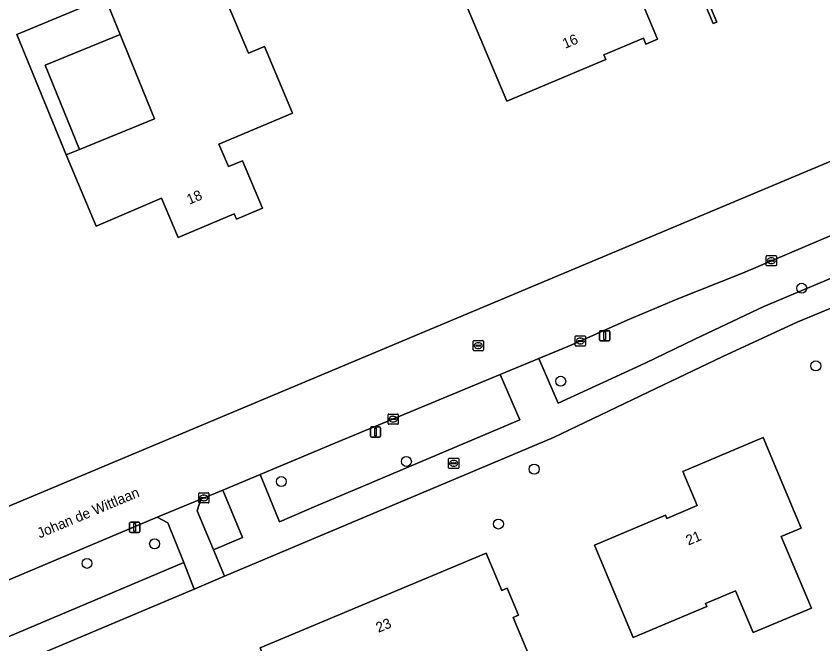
# Model space of a CAD drawing. Extents: x 162417 to 163722, y 384268 to 385417.
# Drawn here: x 163210.5 to 163289.6, y 384911.4 to 384972.9 of the extents above; entities that cross this region are included whole.
import ezdxf

# ---------------------------------------------------------------- set-up
doc = ezdxf.new("R2010")
doc.units = 0
for name, color, linetype in [('IMGEO_Boom', 7, 'Continuous'), ('IMGEO_Brandkraan', 7, 'Continuous'), ('IMGEO_Erf', 7, 'Continuous'), ('IMGEO_Groenvoorziening', 7, 'Continuous'), ('IMGEO_Kolk', 7, 'Continuous'), ('IMGEO_Lichtmast', 7, 'Continuous'), ('IMGEO_Muur', 7, 'Continuous'), ('IMGEO_Openbare_ruimte_label', 7, 'Continuous'), ('IMGEO_Pand', 7, 'Continuous'), ('IMGEO_Pand_nummerreeks', 7, 'Continuous'), ('IMGEO_Rijbaan_lokaal_gesloten', 7, 'Continuous'), ('IMGEO_Rioolput', 7, 'Continuous'), ('IMGEO_Voetpad_open', 7, 'Continuous')]:
    doc.layers.add(name, color=color, linetype=linetype)

msp = doc.modelspace()

# ---------------------------------------------------------------- linework, layer by layer
at = {"layer": 'IMGEO_Boom'}
for centre in [(163287.481, 384946.258), (163288.864, 384938.646), (163263.862, 384937.143), (163248.734, 384929.281), (163261.261, 384928.519), (163236.482, 384927.307), (163257.755, 384923.144), (163224.061, 384921.205), (163217.435, 384919.286)]:
    msp.add_circle(centre, 0.489, dxfattribs=at)
at = {"layer": 'IMGEO_Brandkraan'}
for p, q in [((163252.865, 384928.668), (163252.865, 384929.52)), ((163252.94, 384929.594), (163253.792, 384929.594)), ((163253.124, 384929.088), (163253.124, 384929.1)), ((163253.562, 384929.051), (163253.164, 384929.051)), ((163253.167, 384929.137), (163253.565, 384929.137)), ((163253.353, 384929.374), (163253.378, 384929.374)), ((163253.608, 384929.1), (163253.608, 384929.088)), ((163253.866, 384929.52), (163253.866, 384928.668)), ((163253.792, 384928.594), (163252.94, 384928.594)), ((163253.376, 384928.814), (163253.351, 384928.814))]:
    msp.add_line(p, q, dxfattribs=at)
for points in [[(163252.865, 384928.668), (163252.865, 384929.52)], [(163252.94, 384929.594), (163253.792, 384929.594)], [(163253.866, 384929.52), (163253.866, 384928.668)], [(163253.792, 384928.594), (163252.94, 384928.594)]]:
    msp.add_lwpolyline(points, dxfattribs=at)
for centre, radius, start, end in [((163252.942, 384929.518), 0.0765, 91.55205, 178.44795), ((163252.942, 384929.518), 0.0765, 91.55205, 178.44795), ((163253.164, 384929.097), 0.0403, 85.87752, 175.75265), ((163253.161, 384929.087), 0.0366, 178.93798, 274.71019), ((163253.565, 384929.094), 0.043, 264.86636, 352.45326), ((163253.569, 384929.099), 0.0386, 1.73085, 96.63898), ((163253.79, 384929.518), 0.0765, 1.55205, 88.44795), ((163253.79, 384929.518), 0.0765, 1.55205, 88.44795), ((163252.942, 384928.67), 0.0765, 181.55205, 268.44795), ((163252.942, 384928.67), 0.0765, 181.55205, 268.44795), ((163253.79, 384928.67), 0.0765, 271.55205, 358.44795), ((163253.79, 384928.67), 0.0765, 271.55205, 358.44795)]:
    msp.add_arc(centre, radius, start, end, dxfattribs=at)
for centre, major_axis, ratio, start_param, end_param in [((163253.352, 384929.094), (-0.387, 0.002), 0.722429, 4.712389, 7.853982), ((163253.377, 384929.094), (-0.39, 0.002), 0.717154, 1.570796, 4.712389)]:
    msp.add_ellipse(centre, major_axis=major_axis, ratio=ratio, start_param=start_param, end_param=end_param, dxfattribs=at)
at = {"layer": 'IMGEO_Erf'}
for points in [[(163318.553, 385000), (163308.966, 385023.36), (163277.359, 385010.294), (163269.662, 385007.068), (163253.071, 385000), (163231.527, 384990.762), (163201.717, 384977.798), (163182.103, 384971.2), (163157.341, 384961.784), (163158.508, 384959.069), (163175.467, 384919.624), (163175.758, 384919.851), (163183.667, 384913.961), (163328.962, 384974.963)], [(163248.575, 384988.36), (163256.137, 384991.526), (163267.304, 384996.224), (163272.166, 384984.668), (163273.711, 384985.318), (163275.903, 384980.108), (163279.166, 384972.35), (163278.799, 384972.196), (163275.535, 384979.953), (163270.366, 384977.778), (163273.36, 384970.663), (163272.211, 384970.18), (163271.968, 384970.759), (163268.093, 384969.129), (163268.289, 384968.662), (163258.579, 384964.577), (163254.537, 384974.183), (163262.051, 384977.344), (163258.091, 384986.755), (163250.58, 384983.595)], [(163233.268, 384969.279), (163234.833, 384969.94), (163237.585, 384963.428), (163230.37, 384960.379), (163231.3, 384958.176), (163232.664, 384958.752), (163234.624, 384954.112), (163232.08, 384953.037), (163231.861, 384953.558), (163226.369, 384951.237), (163224.75, 384955.068), (163218.327, 384952.354), (163215.383, 384959.323), (163210.565, 384971.113), (163219.208, 384974.765), (163229.171, 384978.975)], [(163220.693, 384971.128), (163219.208, 384974.765), (163210.565, 384971.113), (163215.383, 384959.323), (163216.704, 384959.862), (163213.332, 384968.124)], [(163224.065, 384962.867), (163220.693, 384971.128), (163213.332, 384968.124), (163216.704, 384959.862)], [(163270.968, 384912.011), (163269.098, 384916.452), (163267.157, 384921.06), (163274.138, 384924), (163274.264, 384923.701), (163277.248, 384924.957), (163275.838, 384928.304), (163283.695, 384931.613), (163285.635, 384927.005), (163287.428, 384922.748), (163285.474, 384921.925), (163288.431, 384914.903), (163282.726, 384912.501), (163281.002, 384916.594), (163278.053, 384915.352), (163278.181, 384915.048)], [(163239.794, 384898.772), (163240.168, 384897.877), (163239.882, 384897.758), (163239.511, 384898.654), (163234.398, 384911.008), (163256.549, 384920.277), (163258.078, 384916.624), (163258.604, 384916.848), (163259.726, 384914.195), (163259.201, 384913.973), (163261.707, 384907.983), (163259.954, 384907.249), (163260.166, 384906.742), (163255.803, 384904.917), (163254.792, 384907.334), (163255.308, 384907.55), (163254.934, 384908.445), (163254.648, 384908.325), (163254.47, 384908.749), (163248.723, 384906.345), (163250.089, 384903.079)]]:
    msp.add_lwpolyline(points, close=True, dxfattribs=at)
msp.add_lwpolyline([(163355.108, 384922.849), (163338.205, 384963.202), (163332.037, 384960.636), (163331.845, 384960.556), (163328.115, 384959.004), (163309.804, 384951.385), (163305.952, 384950.098), (163301.519, 384948.918), (163287.113, 384942.953), (163279.759, 384939.573), (163273.176, 384936.418), (163263.164, 384931.62), (163230.9, 384918.02), (163227.943, 384916.773), (163202.03, 384905.85), (163198.14, 384904.21), (163175.984, 384894.871), (163189.317, 384805.604)], dxfattribs=at)
at = {"layer": 'IMGEO_Groenvoorziening'}
for points in [[(163301.107, 384951.742), (163304.831, 384952.792), (163303.472, 384956.057), (163302.496, 384956.594), (163281.667, 384947.744), (163275.345, 384945.212), (163270.37, 384943.11), (163264.949, 384940.721), (163261.728, 384939.38), (163263.626, 384934.994), (163272.133, 384938.907), (163277.01, 384941.272), (163283.774, 384944.468)], [(163259.852, 384933.342), (163257.919, 384937.794), (163241.735, 384931.056), (163238.069, 384929.529), (163234.402, 384928.003), (163236.298, 384923.37), (163239.927, 384924.92), (163243.638, 384926.483)], [(163232.676, 384921.822), (163230.736, 384926.477), (163228.587, 384925.583), (163228.227, 384924.429), (163229.822, 384920.603)], [(163200.97, 384908.409), (163226.912, 384919.359), (163225.352, 384923.271), (163224.3, 384923.826), (163200.018, 384913.546), (163199.446, 384912.087)]]:
    msp.add_lwpolyline(points, close=True, dxfattribs=at)
at = {"layer": 'IMGEO_Kolk'}
for p, q in [((163284.077, 384949.45), (163284.929, 384949.45)), ((163284.002, 384948.524), (163284.002, 384949.376)), ((163284.261, 384948.944), (163284.261, 384948.956)), ((163284.699, 384948.907), (163284.301, 384948.907)), ((163284.304, 384948.993), (163284.702, 384948.993)), ((163284.513, 384948.67), (163284.488, 384948.67)), ((163284.49, 384949.23), (163284.515, 384949.23)), ((163284.745, 384948.956), (163284.745, 384948.944)), ((163285.003, 384949.376), (163285.003, 384948.524)), ((163284.929, 384948.45), (163284.077, 384948.45)), ((163265.361, 384941.591), (163266.213, 384941.591)), ((163265.286, 384940.665), (163265.286, 384941.517)), ((163265.545, 384941.085), (163265.545, 384941.097)), ((163265.983, 384941.048), (163265.585, 384941.048)), ((163265.588, 384941.134), (163265.986, 384941.134)), ((163265.797, 384940.811), (163265.772, 384940.811)), ((163265.774, 384941.371), (163265.799, 384941.371)), ((163266.029, 384941.097), (163266.029, 384941.085)), ((163266.287, 384941.517), (163266.287, 384940.665)), ((163266.213, 384940.591), (163265.361, 384940.591)), ((163246.936, 384932.998), (163246.936, 384933.85)), ((163247.011, 384933.924), (163247.863, 384933.924)), ((163247.424, 384933.704), (163247.449, 384933.704)), ((163247.937, 384933.85), (163247.937, 384932.998)), ((163247.863, 384932.924), (163247.011, 384932.924)), ((163247.195, 384933.418), (163247.195, 384933.43)), ((163247.633, 384933.381), (163247.235, 384933.381)), ((163247.238, 384933.467), (163247.636, 384933.467)), ((163247.447, 384933.144), (163247.422, 384933.144)), ((163247.679, 384933.43), (163247.679, 384933.418)), ((163228.381, 384925.281), (163228.381, 384926.133)), ((163228.456, 384926.207), (163229.308, 384926.207)), ((163228.683, 384925.75), (163229.081, 384925.75)), ((163228.869, 384925.987), (163228.894, 384925.987)), ((163229.382, 384926.133), (163229.382, 384925.281)), ((163229.308, 384925.207), (163228.456, 384925.207)), ((163228.64, 384925.701), (163228.64, 384925.713)), ((163229.078, 384925.664), (163228.68, 384925.664)), ((163228.892, 384925.427), (163228.867, 384925.427)), ((163229.124, 384925.713), (163229.124, 384925.701))]:
    msp.add_line(p, q, dxfattribs=at)
for points in [[(163284.077, 384949.45), (163284.929, 384949.45)], [(163284.002, 384948.524), (163284.002, 384949.376)], [(163285.003, 384949.376), (163285.003, 384948.524)], [(163284.929, 384948.45), (163284.077, 384948.45)], [(163265.361, 384941.591), (163266.213, 384941.591)], [(163265.286, 384940.665), (163265.286, 384941.517)], [(163266.287, 384941.517), (163266.287, 384940.665)], [(163266.213, 384940.591), (163265.361, 384940.591)], [(163246.936, 384932.998), (163246.936, 384933.85)], [(163247.011, 384933.924), (163247.863, 384933.924)], [(163247.937, 384933.85), (163247.937, 384932.998)], [(163247.863, 384932.924), (163247.011, 384932.924)], [(163228.381, 384925.281), (163228.381, 384926.133)], [(163228.456, 384926.207), (163229.308, 384926.207)], [(163229.382, 384926.133), (163229.382, 384925.281)], [(163229.308, 384925.207), (163228.456, 384925.207)]]:
    msp.add_lwpolyline(points, dxfattribs=at)
for centre, radius, start, end in [((163284.079, 384949.374), 0.0765, 91.55205, 178.44795), ((163284.079, 384949.374), 0.0765, 91.55205, 178.44795), ((163284.927, 384949.374), 0.0765, 1.55205, 88.44795), ((163284.927, 384949.374), 0.0765, 1.55205, 88.44795), ((163284.301, 384948.953), 0.0403, 85.87752, 175.75265), ((163284.298, 384948.943), 0.0366, 178.93798, 274.71019), ((163284.702, 384948.95), 0.043, 264.86636, 352.45326), ((163284.706, 384948.955), 0.0386, 1.73085, 96.63898), ((163284.079, 384948.526), 0.0765, 181.55205, 268.44795), ((163284.079, 384948.526), 0.0765, 181.55205, 268.44795), ((163284.927, 384948.526), 0.0765, 271.55205, 358.44795), ((163284.927, 384948.526), 0.0765, 271.55205, 358.44795), ((163265.363, 384941.515), 0.0765, 91.55205, 178.44795), ((163265.363, 384941.515), 0.0765, 91.55205, 178.44795), ((163266.211, 384941.515), 0.0765, 1.55205, 88.44795), ((163266.211, 384941.515), 0.0765, 1.55205, 88.44795), ((163265.585, 384941.094), 0.0403, 85.87752, 175.75265), ((163265.582, 384941.084), 0.0366, 178.93798, 274.71019), ((163265.986, 384941.091), 0.043, 264.86636, 352.45326), ((163265.99, 384941.096), 0.0386, 1.73085, 96.63898), ((163265.363, 384940.667), 0.0765, 181.55205, 268.44795), ((163265.363, 384940.667), 0.0765, 181.55205, 268.44795), ((163266.211, 384940.667), 0.0765, 271.55205, 358.44795), ((163266.211, 384940.667), 0.0765, 271.55205, 358.44795), ((163247.013, 384933.848), 0.0765, 91.55205, 178.44795), ((163247.013, 384933.848), 0.0765, 91.55205, 178.44795), ((163247.861, 384933.848), 0.0765, 1.55205, 88.44795), ((163247.861, 384933.848), 0.0765, 1.55205, 88.44795), ((163247.013, 384933), 0.0765, 181.55205, 268.44795), ((163247.013, 384933), 0.0765, 181.55205, 268.44795), ((163247.235, 384933.427), 0.0403, 85.87752, 175.75265), ((163247.232, 384933.417), 0.0366, 178.93798, 274.71019), ((163247.636, 384933.424), 0.043, 264.86636, 352.45326), ((163247.64, 384933.429), 0.0386, 1.73085, 96.63898), ((163247.861, 384933), 0.0765, 271.55205, 358.44795), ((163247.861, 384933), 0.0765, 271.55205, 358.44795), ((163228.458, 384926.131), 0.0765, 91.55205, 178.44795), ((163228.458, 384926.131), 0.0765, 91.55205, 178.44795), ((163228.68, 384925.71), 0.0403, 85.87752, 175.75265), ((163229.085, 384925.712), 0.0386, 1.73085, 96.63898), ((163229.306, 384926.131), 0.0765, 1.55205, 88.44795), ((163229.306, 384926.131), 0.0765, 1.55205, 88.44795), ((163228.458, 384925.283), 0.0765, 181.55205, 268.44795), ((163228.458, 384925.283), 0.0765, 181.55205, 268.44795), ((163228.677, 384925.7), 0.0366, 178.93798, 274.71019), ((163229.081, 384925.707), 0.043, 264.86636, 352.45326), ((163229.306, 384925.283), 0.0765, 271.55205, 358.44795), ((163229.306, 384925.283), 0.0765, 271.55205, 358.44795)]:
    msp.add_arc(centre, radius, start, end, dxfattribs=at)
for centre, major_axis, ratio, start_param, end_param in [((163284.489, 384948.95), (-0.387, 0.002), 0.722429, 4.712389, 7.853982), ((163284.514, 384948.95), (-0.39, 0.002), 0.717154, 1.570796, 4.712389), ((163265.773, 384941.091), (-0.387, 0.002), 0.722429, 4.712389, 7.853982), ((163265.798, 384941.091), (-0.39, 0.002), 0.717154, 1.570796, 4.712389), ((163247.423, 384933.424), (-0.387, 0.002), 0.722429, 4.712389, 7.853982), ((163247.448, 384933.424), (-0.39, 0.002), 0.717154, 1.570796, 4.712389), ((163228.868, 384925.707), (-0.387, 0.002), 0.722429, 4.712389, 7.853982), ((163228.893, 384925.707), (-0.39, 0.002), 0.717154, 1.570796, 4.712389)]:
    msp.add_ellipse(centre, major_axis=major_axis, ratio=ratio, start_param=start_param, end_param=end_param, dxfattribs=at)
at = {"layer": 'IMGEO_Lichtmast'}
for p, q in [((163267.672, 384941.193), (163267.672, 384941.993)), ((163267.672, 384941.993), (163267.672, 384941.193)), ((163267.772, 384942.093), (163268.562, 384942.093)), ((163268.562, 384942.093), (163267.772, 384942.093)), ((163268.662, 384941.993), (163268.662, 384941.193)), ((163268.662, 384941.193), (163268.662, 384941.993)), ((163268.562, 384941.093), (163267.772, 384941.093)), ((163267.772, 384941.093), (163268.562, 384941.093)), ((163245.212, 384931.755), (163245.212, 384932.555)), ((163245.212, 384932.555), (163245.212, 384931.755)), ((163245.312, 384932.655), (163246.102, 384932.655)), ((163246.102, 384932.655), (163245.312, 384932.655)), ((163246.202, 384932.555), (163246.202, 384931.755)), ((163246.202, 384931.755), (163246.202, 384932.555)), ((163246.102, 384931.655), (163245.312, 384931.655)), ((163245.312, 384931.655), (163246.102, 384931.655)), ((163221.616, 384922.425), (163221.616, 384923.225)), ((163221.616, 384923.225), (163221.616, 384922.425)), ((163221.716, 384923.325), (163222.506, 384923.325)), ((163222.506, 384923.325), (163221.716, 384923.325)), ((163222.606, 384923.225), (163222.606, 384922.425)), ((163222.606, 384922.425), (163222.606, 384923.225)), ((163222.506, 384922.325), (163221.716, 384922.325)), ((163221.716, 384922.325), (163222.506, 384922.325))]:
    msp.add_line(p, q, dxfattribs=at)
for points in [[(163268.092, 384941.968), (163268.242, 384941.968), (163268.242, 384941.218), (163268.092, 384941.218), (163268.092, 384941.968)], [(163245.632, 384932.53), (163245.782, 384932.53), (163245.782, 384931.78), (163245.632, 384931.78), (163245.632, 384932.53)], [(163222.036, 384923.2), (163222.186, 384923.2), (163222.186, 384922.45), (163222.036, 384922.45), (163222.036, 384923.2)]]:
    msp.add_lwpolyline(points, dxfattribs=at)
for centre, start, end in [((163267.772, 384941.993), 90, 180), ((163267.772, 384941.993), 90, 180), ((163268.562, 384941.993), 0, 90), ((163268.562, 384941.993), 360, 90), ((163267.772, 384941.193), 180, 270), ((163267.772, 384941.193), 180, 270), ((163268.562, 384941.193), 270, 0), ((163268.562, 384941.193), 270, 0), ((163245.312, 384932.555), 90, 180), ((163245.312, 384932.555), 90, 180), ((163246.102, 384932.555), 0, 90), ((163246.102, 384932.555), 360, 90), ((163245.312, 384931.755), 180, 270), ((163245.312, 384931.755), 180, 270), ((163246.102, 384931.755), 270, 0), ((163246.102, 384931.755), 270, 0), ((163221.716, 384923.225), 90, 180), ((163221.716, 384923.225), 90, 180), ((163222.506, 384923.225), 0, 90), ((163222.506, 384923.225), 360, 90), ((163221.716, 384922.425), 180, 270), ((163221.716, 384922.425), 180, 270), ((163222.506, 384922.425), 270, 0), ((163222.506, 384922.425), 270, 0)]:
    msp.add_arc(centre, 0.1, start, end, dxfattribs=at)
at = {"layer": 'IMGEO_Muur'}
msp.add_lwpolyline([(163275.903, 384980.108), (163275.535, 384979.953), (163278.799, 384972.196), (163279.166, 384972.35)], close=True, dxfattribs=at)
at = {"layer": 'IMGEO_Pand'}
for points in [[(163268.289, 384968.662), (163268.093, 384969.129), (163271.968, 384970.759), (163272.211, 384970.18), (163273.36, 384970.663), (163270.366, 384977.778), (163275.535, 384979.953), (163275.903, 384980.108), (163273.711, 384985.318), (163272.166, 384984.668), (163267.304, 384996.224), (163256.137, 384991.526), (163248.575, 384988.36), (163250.58, 384983.595), (163258.091, 384986.755), (163262.051, 384977.344), (163254.537, 384974.183), (163258.579, 384964.577)], [(163237.585, 384963.428), (163234.833, 384969.94), (163233.268, 384969.279), (163229.171, 384978.975), (163219.208, 384974.765), (163220.693, 384971.128), (163224.065, 384962.867), (163216.704, 384959.862), (163215.383, 384959.323), (163218.327, 384952.354), (163224.75, 384955.068), (163226.369, 384951.237), (163231.861, 384953.558), (163232.08, 384953.037), (163234.624, 384954.112), (163232.664, 384958.752), (163231.3, 384958.176), (163230.37, 384960.379)], [(163270.968, 384912.011), (163278.181, 384915.048), (163278.053, 384915.352), (163281.002, 384916.594), (163282.726, 384912.501), (163288.431, 384914.903), (163285.474, 384921.925), (163287.428, 384922.748), (163285.635, 384927.005), (163283.695, 384931.613), (163275.838, 384928.304), (163277.248, 384924.957), (163274.264, 384923.701), (163274.138, 384924), (163267.157, 384921.06), (163269.098, 384916.452)], [(163239.794, 384898.772), (163250.089, 384903.079), (163248.723, 384906.345), (163254.47, 384908.749), (163254.648, 384908.325), (163254.934, 384908.445), (163255.308, 384907.55), (163254.792, 384907.334), (163255.803, 384904.917), (163260.166, 384906.742), (163259.954, 384907.249), (163261.707, 384907.983), (163259.201, 384913.973), (163259.726, 384914.195), (163258.604, 384916.848), (163258.078, 384916.624), (163256.549, 384920.277), (163234.398, 384911.008), (163239.511, 384898.654)]]:
    msp.add_lwpolyline(points, close=True, dxfattribs=at)
at = {"layer": 'IMGEO_Rijbaan_lokaal_gesloten'}
for points in [[(163337.564, 384978.789), (163336.54, 384978.154), (163336.199, 384978.01), (163333.911, 384977.041), (163328.962, 384974.963), (163183.667, 384913.961), (163186.272, 384907.759), (163194.231, 384911.102), (163200.018, 384913.546), (163224.3, 384923.826)], [(163224.3, 384923.826), (163228.587, 384925.583), (163230.736, 384926.477), (163234.402, 384928.003), (163238.069, 384929.529), (163241.735, 384931.056), (163257.919, 384937.794), (163261.728, 384939.38), (163264.949, 384940.721), (163270.37, 384943.11), (163275.345, 384945.212), (163281.667, 384947.744), (163302.496, 384956.594), (163307.598, 384958.773), (163324.469, 384965.836), (163329.492, 384967.896), (163329.596, 384967.938), (163335.648, 384970.48), (163335.853, 384970.566), (163338.251, 384971.574), (163338.433, 384971.65), (163340.1, 384972.378)]]:
    msp.add_lwpolyline(points, dxfattribs=at)
at = {"layer": 'IMGEO_Rioolput'}
for p, q in [((163255.28, 384940.208), (163255.28, 384941.06)), ((163255.355, 384941.134), (163256.207, 384941.134)), ((163255.768, 384940.914), (163255.793, 384940.914)), ((163256.281, 384941.06), (163256.281, 384940.208)), ((163256.207, 384940.134), (163255.355, 384940.134)), ((163255.539, 384940.628), (163255.539, 384940.64)), ((163255.977, 384940.591), (163255.579, 384940.591)), ((163255.582, 384940.677), (163255.98, 384940.677)), ((163255.791, 384940.354), (163255.766, 384940.354)), ((163256.023, 384940.64), (163256.023, 384940.628))]:
    msp.add_line(p, q, dxfattribs=at)
for points in [[(163255.28, 384940.208), (163255.28, 384941.06)], [(163255.355, 384941.134), (163256.207, 384941.134)], [(163256.281, 384941.06), (163256.281, 384940.208)], [(163256.207, 384940.134), (163255.355, 384940.134)]]:
    msp.add_lwpolyline(points, dxfattribs=at)
for centre, radius, start, end in [((163255.357, 384941.058), 0.0765, 91.55205, 178.44795), ((163255.357, 384941.058), 0.0765, 91.55205, 178.44795), ((163256.205, 384941.058), 0.0765, 1.55205, 88.44795), ((163256.205, 384941.058), 0.0765, 1.55205, 88.44795), ((163255.357, 384940.21), 0.0765, 181.55205, 268.44795), ((163255.357, 384940.21), 0.0765, 181.55205, 268.44795), ((163255.579, 384940.637), 0.0403, 85.87752, 175.75265), ((163255.576, 384940.627), 0.0366, 178.93798, 274.71019), ((163255.98, 384940.634), 0.043, 264.86636, 352.45326), ((163255.984, 384940.639), 0.0386, 1.73085, 96.63898), ((163256.205, 384940.21), 0.0765, 271.55205, 358.44795), ((163256.205, 384940.21), 0.0765, 271.55205, 358.44795)]:
    msp.add_arc(centre, radius, start, end, dxfattribs=at)
for centre, major_axis, ratio, start_param, end_param in [((163255.767, 384940.634), (-0.387, 0.002), 0.722429, 4.712389, 7.853982), ((163255.792, 384940.634), (-0.39, 0.002), 0.717154, 1.570796, 4.712389)]:
    msp.add_ellipse(centre, major_axis=major_axis, ratio=ratio, start_param=start_param, end_param=end_param, dxfattribs=at)
at = {"layer": 'IMGEO_Voetpad_open'}
for points in [[(163301.519, 384948.918), (163305.952, 384950.098), (163304.831, 384952.792), (163301.107, 384951.742), (163283.774, 384944.468), (163277.01, 384941.272), (163272.133, 384938.907), (163263.626, 384934.994), (163261.728, 384939.38), (163257.919, 384937.794), (163259.852, 384933.342), (163243.638, 384926.483), (163239.927, 384924.92), (163236.298, 384923.37), (163234.402, 384928.003), (163230.736, 384926.477), (163232.676, 384921.822), (163229.822, 384920.603), (163230.9, 384918.02), (163263.164, 384931.62), (163273.176, 384936.418), (163279.759, 384939.573), (163287.113, 384942.953)], [(163226.912, 384919.359), (163227.943, 384916.773), (163230.9, 384918.02), (163229.822, 384920.603), (163228.227, 384924.429), (163228.587, 384925.583), (163224.3, 384923.826), (163225.352, 384923.271)], [(163202.03, 384905.85), (163227.943, 384916.773), (163226.912, 384919.359), (163200.97, 384908.409)]]:
    msp.add_lwpolyline(points, close=True, dxfattribs=at)

# ---------------------------------------------------------------- texts
at = {"layer": 'IMGEO_Openbare_ruimte_label'}
msp.add_text('Johan de Wittlaan', height=1, rotation=22.76973, dxfattribs=at).set_placement((163212.798, 384921.729))
at = {"layer": 'IMGEO_Pand_nummerreeks'}
for s, rotation, p in [('16', 22.81518, (163264.291, 384969.714)), ('18', 22.90685, (163227.46, 384954.433)), ('21', 22.82679, (163276.371, 384921.029)), ('23', 22.77507, (163245.998, 384912.474))]:
    msp.add_text(s, height=1, rotation=rotation, dxfattribs=at).set_placement(p)

doc.saveas('drawing.dxf')
